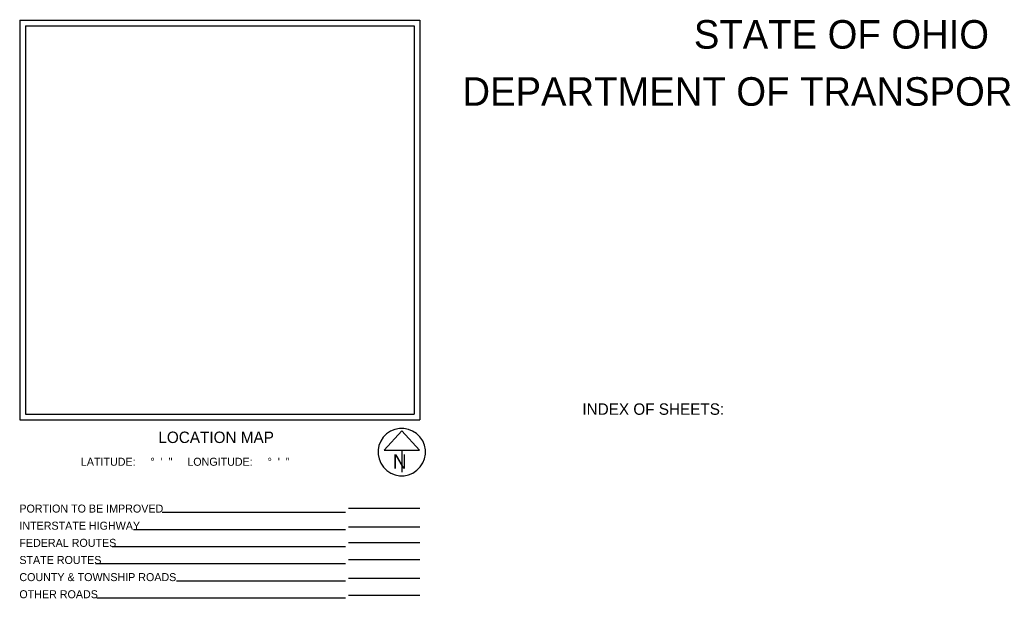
# Model space of a CAD drawing. Extents: x 0 to 70.2, y 0 to 31.4.
# Drawn here: x 40.23 to 57.45, y 21.14 to 31.27 of the extents above; entities that cross this region are included whole.
import ezdxf

# ---------------------------------------------------------------- set-up
doc = ezdxf.new("R2010")
doc.units = 0
doc.layers.add('SH_Data', color=7, linetype='Continuous')
doc.layers.add('SH_Text', color=7, linetype='Continuous')

msp = doc.modelspace()

# ---------------------------------------------------------------- linework, layer by layer
at = {"layer": 'SH_Data'}
for p, q in [((40.227, 31.263), (47.227, 31.263)), ((40.227, 31.263), (40.227, 24.263)), ((47.227, 31.263), (47.227, 24.263)), ((40.327, 31.163), (40.327, 24.363)), ((40.327, 31.163), (47.127, 31.163)), ((47.127, 31.163), (47.127, 24.363)), ((40.327, 24.363), (47.127, 24.363)), ((40.327, 24.363), (40.327, 24.363)), ((40.227, 24.263), (47.227, 24.263)), ((46.911, 24.072), (46.603, 23.731)), ((47.219, 23.731), (46.911, 24.072)), ((46.603, 23.731), (47.219, 23.731)), ((46.911, 23.731), (46.911, 23.344)), ((46.911, 23.698), (46.911, 23.698)), ((46.911, 23.698), (46.911, 23.698)), ((45.927, 22.639), (42.72, 22.639)), ((45.977, 22.718), (47.227, 22.718)), ((45.927, 22.339), (42.216, 22.339)), ((47.227, 22.384), (45.977, 22.384)), ((47.227, 22.112), (45.977, 22.112)), ((45.927, 22.039), (41.846, 22.039)), ((45.927, 21.739), (41.555, 21.739)), ((47.227, 21.812), (45.977, 21.812)), ((45.927, 21.439), (42.972, 21.439)), ((47.227, 21.485), (45.977, 21.485)), ((45.927, 21.139), (41.574, 21.139)), ((47.227, 21.185), (45.977, 21.185))]:
    msp.add_line(p, q, dxfattribs=at)
msp.add_arc((46.911, 23.698), 0.415, 129.7798, 129.7633, dxfattribs=at)

# ---------------------------------------------------------------- texts
msp.add_text('N', height=0.25, dxfattribs=at).set_placement((46.756, 23.407))
at = {"layer": 'SH_Text'}
for s, height, p in [('STATE OF OHIO', 0.5, (52.022, 30.763)), ('DEPARTMENT OF TRANSPORTATION', 0.5, (47.973, 29.763)), ('INDEX OF SHEETS:', 0.2, (50.071, 24.351)), ('LOCATION MAP', 0.2, (42.653, 23.857)), ('LATITUDE:     °  \'  "     LONGITUDE:     °  \'  "', 0.14, (41.297, 23.459)), ('PORTION TO BE IMPROVED', 0.14, (40.221, 22.639)), ('INTERSTATE HIGHWAY', 0.14, (40.221, 22.339)), ('FEDERAL ROUTES', 0.14, (40.221, 22.039)), ('STATE ROUTES', 0.14, (40.221, 21.739)), ('COUNTY & TOWNSHIP ROADS', 0.14, (40.221, 21.439)), ('OTHER ROADS', 0.14, (40.221, 21.139))]:
    msp.add_text(s, height=height, dxfattribs=at).set_placement(p)

doc.saveas('drawing.dxf')
